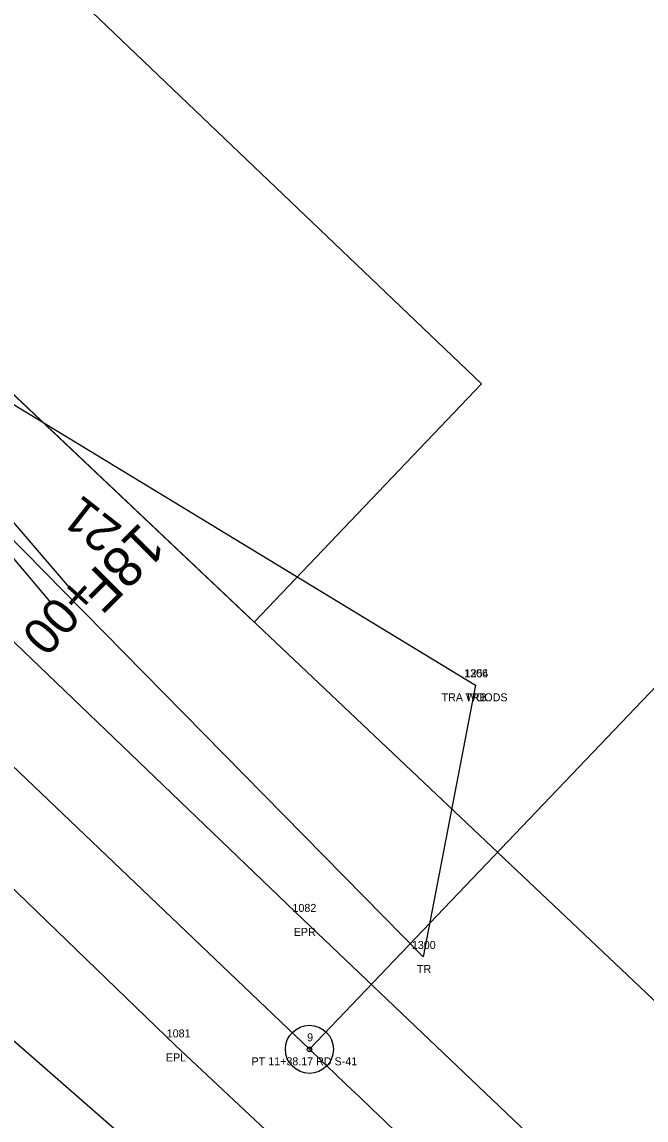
# Model space of a CAD drawing. Extents: x 1812113 to 1819860, y 1177290 to 1181185.
# Drawn here: x 1813930 to 1814007.9, y 1178506.5 to 1178643.7 of the extents above; entities that cross this region are included whole.
import ezdxf

# ---------------------------------------------------------------- set-up
doc = ezdxf.new("R2010")
doc.units = 0
for name, color, linetype in [('RD_EX_DV_Prop', 7, 'Continuous'), ('RD_EX_Road', 7, 'Continuous'), ('RD_EX_Road_txCode', 7, 'Continuous'), ('RD_EX_VEG', 7, 'Continuous'), ('RD_EX_VEG_txCode', 7, 'Continuous'), ('RD_HC_CL', 7, 'Continuous'), ('RD_HC_Data', 7, 'Continuous'), ('RD_HC_txCode', 7, 'Continuous'), ('RD_PD_ALT1_LnLine', 7, 'Continuous'), ('RD_PD_ALT1_TrvlWay', 7, 'Continuous'), ('RD_PD_CstnLmt', 7, 'Continuous'), ('RD_PD_DR_ErosCtrl', 7, 'Continuous'), ('RD_PD_RW', 7, 'Continuous'), ('RD_SMD_Locator', 7, 'Continuous')]:
    doc.layers.add(name, color=color, linetype=linetype)

msp = doc.modelspace()

# ---------------------------------------------------------------- linework, layer by layer
at = {"layer": 'RD_EX_DV_Prop'}
msp.add_line((1814011.17, 1178519.35), (1813854.67, 1178667.32), dxfattribs=at)
at = {"layer": 'RD_EX_Road'}
for p, q in [((1813949.15, 1178515.86), (1813911.94, 1178551.77)), ((1813986.47, 1178480.85), (1813949.15, 1178515.86))]:
    msp.add_line(p, q, dxfattribs=at)
msp.add_lwpolyline([(1814076.45, 1178427.4), (1814038.86, 1178461.87), (1814001.83, 1178496.62), (1813965.15, 1178531.54), (1813928.08, 1178567.1), (1813892.01, 1178601.23), (1813854.54, 1178636.51), (1813817.44, 1178670.03), (1813779.87, 1178701.64)], dxfattribs=at)
at = {"layer": 'RD_EX_VEG'}
for points in [[(1813964.65, 1178448.48), (1813984.61, 1178463.55), (1813943.71, 1178503.46), (1813904.65, 1178537.57), (1813863.79, 1178578.71), (1813833.99, 1178603.93), (1813823.24, 1178594.53), (1813964.65, 1178448.48)], [(1813986.62, 1178560.85), (1813980.11, 1178526.91), (1813915.24, 1178592.82), (1813918.96, 1178601.96), (1813986.62, 1178560.85)]]:
    msp.add_lwpolyline(points, dxfattribs=at)
at = {"layer": 'RD_HC_CL'}
msp.add_line((1813965.88, 1178515.37), (1813886.05, 1178591.55), dxfattribs=at)
msp.add_arc((1817921.84, 1182660.75), 5730.08, 226.33932, 227.720866, dxfattribs=at)
at = {"layer": 'RD_HC_Data'}
msp.add_line((1813965.88, 1178515.37), (1814045.93, 1178599.26), dxfattribs=at)
for radius in [3, 0.282]:
    msp.add_circle((1813965.88, 1178515.37), radius, dxfattribs=at)
at = {"layer": 'RD_PD_ALT1_LnLine'}
for p, q in [((1813958.96, 1178568.72), (1813854.67, 1178667.32)), ((1813937.83, 1178645.81), (1813987.39, 1178598.51)), ((1813987.39, 1178598.51), (1813958.96, 1178568.72))]:
    msp.add_line(p, q, dxfattribs=at)
at = {"layer": 'RD_PD_CstnLmt'}
msp.add_line((1813933.62, 1178571.14), (1813901.12, 1178609.56), dxfattribs=at)
at = {"layer": 'RD_PD_DR_ErosCtrl'}
msp.add_line((1813935.91, 1178573.07), (1813902.89, 1178611.42), dxfattribs=at)
at = {"layer": 'RD_PD_RW'}
for q in [(1813937.83, 1178645.81), (1813958.96, 1178568.72)]:
    msp.add_line((1813987.39, 1178598.51), q, dxfattribs=at)
at = {"layer": 'RD_SMD_Locator'}
for centre in [(1813986.62, 1178560.85), (1813986.62, 1178560.85), (1813965.15, 1178531.54), (1813980.11, 1178526.91), (1813949.15, 1178515.86), (1813965.88, 1178515.37)]:
    msp.add_circle(centre, 0.001, dxfattribs=at)

# ---------------------------------------------------------------- texts
at = {"layer": 'RD_EX_Road_txCode'}
for s, p in [('1082', (1813963.76, 1178532.54)), ('EPR', (1813963.92, 1178529.54)), ('1081', (1813948.05, 1178516.86)), ('EPL', (1813947.95, 1178513.86))]:
    msp.add_text(s, height=1, dxfattribs=at).set_placement(p)
at = {"layer": 'RD_EX_VEG_txCode'}
for s, p in [('1306', (1813985.21, 1178561.85)), ('1254', (1813985.27, 1178561.85)), ('TRA WOODS', (1813982.39, 1178558.85)), ('TRB', (1813985.35, 1178558.85)), ('1300', (1813978.68, 1178527.91)), ('TR', (1813979.31, 1178524.91))]:
    msp.add_text(s, height=1, dxfattribs=at).set_placement(p)
at = {"layer": 'RD_HC_txCode'}
for s, p in [('9', (1813965.59, 1178516.37)), ('PT 11+38.17 RD S-41', (1813958.65, 1178513.37))]:
    msp.add_text(s, height=1, dxfattribs=at).set_placement(p)
at = {"layer": 'RD_PD_ALT1_TrvlWay'}
msp.add_text('+00', height=4.5, rotation=228.1577, dxfattribs=at).set_placement((1813936.5, 1178574.86))
at = {"layer": 'RD_PD_CstnLmt'}
msp.add_text('18F', height=5, rotation=224.8048, dxfattribs=at).set_placement((1813944.77, 1178581.36))
at = {"layer": 'RD_PD_DR_ErosCtrl'}
msp.add_text('21', height=4.5, rotation=141.9841, dxfattribs=at).set_placement((1813942.69, 1178580.58))

doc.saveas('drawing.dxf')
